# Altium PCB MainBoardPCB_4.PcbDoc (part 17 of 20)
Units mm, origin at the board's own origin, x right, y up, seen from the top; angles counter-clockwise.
Board outline 333.63 x 349.38 mm, 16 copper layers (L1, L2 (GND), L3 (Sign), L4 (GND), L5 (Sign), L6 (PWR/GND), L7(PWR/GND), L8 (Plane_GND), L9 (PWR/GND), L10 (PWR/GND), L11 (PWR/GND), L12 (Sign), L13 (GND), L14 (Sign), L15 (GND), L16), stack 2.502 mm thick; 2205 components, 1648 nets, 8314 pads, 3172 vias.
Unrouted connection lines stored in the file: 5141.
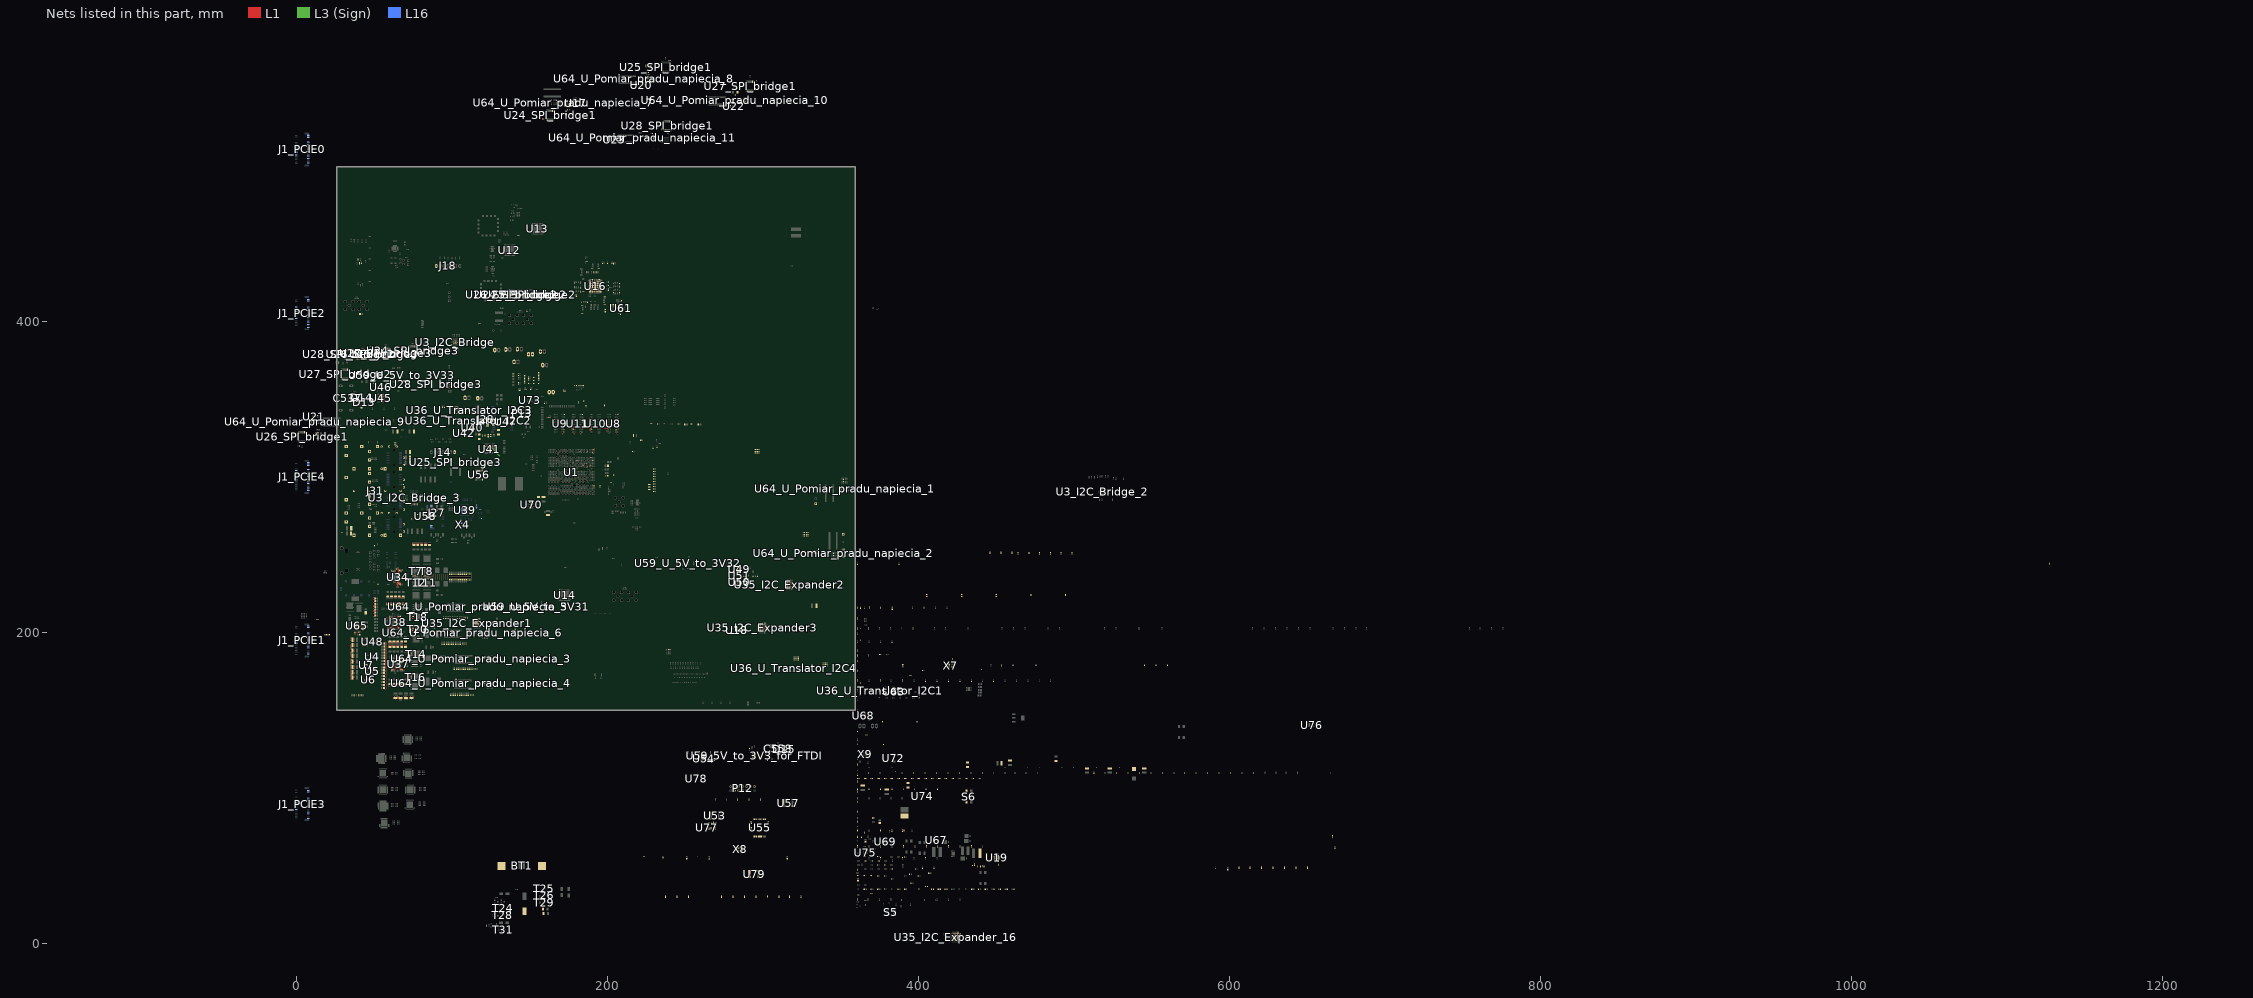
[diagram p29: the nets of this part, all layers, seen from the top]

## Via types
v1: diameter 0.5, hole 0.2, L1 to L16, tented both sides, 1153 vias
v2: diameter 0.5/0.35/0.35/0.35/0.35/0.35/0.35/0.35/0.35/0.35/0.35/0.35/0.35/0.35/0.35/0.5 (per signal layer), hole 0.2, L1 to L16, tented both sides, 548 vias
v3: diameter 0.5, hole 0.2, L1 to L16, 522 vias
v4: diameter 0.5/0.35/0.35/0.35/0.35/0.35/0.35/0.35/0.35/0.35/0.35/0.35/0.35/0.35/0.35/0.5 (per signal layer), hole 0.15, L1 to L16, tented both sides, 266 vias
v5: diameter 0.8, hole 0.4, L1 to L16, tented both sides, 164 vias
v6: diameter 0.35/0/0.35 (per signal layer), hole 0.127, L1 to L3 (Sign), tented both sides, 132 vias
v7: diameter 2.54, hole 1.02, L1 to L16, 125 vias
v8: diameter 1.4, hole 0.5, L1 to L16, tented both sides, 80 vias
v9: diameter 0.35, hole 0.127, L1 to L2 (GND), tented both sides, 36 vias
v10: diameter 0.4, hole 0.2, L1 to L16, 16 vias
v11: diameter 0.25, hole 0.2, L1 to L16, 16 vias
v12: diameter 5, hole 3, L1 to L16, 15 vias
v13: diameter 0.3, hole 0.2, L1 to L16, 15 vias
v14: diameter 0.45, hole 0.15, L1 to L16, 12 vias
v15: diameter 0.5/0.35/0.35/0.35/0.35/0.35/0.35/0.35/0.35/0.35/0.35/0.35/0.35/0.35/0.35/0.45 (per signal layer), hole 0.15, L1 to L16, tented both sides, 10 vias
v16: diameter 0.2/0/0.2 (per signal layer), hole 0.1, L1 to L3 (Sign), tented both sides, 9 vias
v17: diameter 0.4, hole 0.1, L1 to L16, 7 vias
v18: diameter 0.5, hole 0.2, L3 (Sign) to L6 (PWR/GND), tented both sides, 6 vias
v19: diameter 1.65, hole 1.65, L1 to L16, 6 vias
v20: diameter 1.15, hole 1.15, L1 to L16, 6 vias
v21: diameter 0.35/0/0.35 (per signal layer), hole 0.127, L14 (Sign) to L16, tented both sides, 5 vias
v22: diameter 0.2, hole 0.1, L1 to L16, 4 vias
v23: diameter 0.4, hole 0.2, L1 to L16, tented both sides, 2 vias
v24: diameter 0.4, hole 0.15, L1 to L16, 2 vias
v25: diameter 0.508, hole 0.127, L1 to L2 (GND), 2 vias
v26: diameter 0.508, hole 0.127, L2 (GND) to L3 (Sign), 2 vias
v27: diameter 0.5/0.35/0.35/0.35/0.35/0.35/0.35/0.35/0.35/0.35/0.35/0.35/0.35/0.35/0.35/0.5 (per signal layer), hole 0.15, L1 to L16, 2 vias
v28: diameter 0.35, hole 0.127, L3 (Sign) to L6 (PWR/GND), tented both sides, 2 vias
v29: diameter 5.5, hole 3.5, L1 to L16, 1 vias
v30: diameter 0.5/0.35/0.35/0.35/0.35/0.35/0.35/0.35/0.35/0.35/0.35/0.35/0.35/0.35/0.35/0.5 (per signal layer), hole 0.2, L1 to L16, 1 vias
v31: diameter 0.35/0.35/0.35 (per signal layer), hole 0.127, L1 to L3 (Sign), tented both sides, 1 vias
v32: diameter 0.45/0/0.45 (per signal layer), hole 0.15, L1 to L3 (Sign), tented both sides, 1 vias
v33: diameter 0.45/0/0.45 (per signal layer), hole 0.2, L14 (Sign) to L16, tented both sides, 1 vias
v34: diameter 0.35, hole 0.127, L2 (GND) to L3 (Sign), 1 vias
v35: diameter 0.35, hole 0.127, L1 to L2 (GND), 1 vias

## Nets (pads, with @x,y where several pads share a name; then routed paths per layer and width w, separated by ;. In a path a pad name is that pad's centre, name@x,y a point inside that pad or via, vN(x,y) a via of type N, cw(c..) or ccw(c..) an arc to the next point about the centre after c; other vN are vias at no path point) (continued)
eMMC_GND: B1.2 BT1.1 C4.2 C5.2 C6.2 C7.2 C8.1 C9.1 C10.1 C11.1 C12.2 C13.2 C14.2 C15.2 C16.1 C17.1 C18.1 C19.1 C20.1 C21.1 C22.1 C23.1 C24.1 C25.1 C26.1 C27.1 C28.1 C29.1 C30.1 C31.1 C32.1 C33.1 C34.1 C35.1 C37.1 C38.2 C39.1 C40.2 C207.1 C208.2 C209.1 C210.2 C211.1 C212.2 C213.1 C214.2 C215.1 C216.2 C217.1 C218.2 C219.2 C220.2 C221.2 C222.2 C223.1 C224.1 C225.1 C226.1 C227.1 C228.1 C229.1 C230.1 C231.1 C232.1 C233.1 C234.1 C235.1 C236.1 C237.1 C238.1 C239.1 C240.1 C241.1 C242.1 C243.2 C244.2 C245.2 C246.2 C247.1 C248.1 C249.1 C250.1 C251.1 C252.1 C253.1 C254.1 C255.1 C256.1 C257.1 C258.1 C259.1 C260.1 C261.1 C262.1 C263.1 C264.1 C265.1 C266.1 C303_I2C_Bridge.1 C303_I2C_Bridge_2.1 C303_I2C_Bridge_3.1 C304.2 C305.2 C306.2 C307.2 C308.1 C309_U_Pomiar_pradu_napiecia_1.1 C309_U_Pomiar_pradu_napiecia_2.1 C309_U_Pomiar_pradu_napiecia_3.1 C309_U_Pomiar_pradu_napiecia_4.1 C309_U_Pomiar_pradu_napiecia_5.1 C309_U_Pomiar_pradu_napiecia_6.1 C309_U_Pomiar_pradu_napiecia_7.1 C309_U_Pomiar_pradu_napiecia_8.1 C309_U_Pomiar_pradu_napiecia_9.1 C309_U_Pomiar_pradu_napiecia_10.1 C309_U_Pomiar_pradu_napiecia_11.1 C310.1 C311_I2C_Expander1.1 C311_I2C_Expander2.1 C311_I2C_Expander3.1 C311_I2C_Expander?.1 C311_I2C_Expander_10.1 C311_I2C_Expander_11.1 C311_I2C_Expander_12.1 C311_I2C_Expander_13.1 C311_I2C_Expander_14.1 C311_I2C_Expander_15.1 C311_I2C_Expander_16.1 C331.1 C332.1 C347.1 C348.1 C352.1 C353.1 C354.1 C355.1 C358.1 C359.1 C360.1 C361.1 C362.1 C363.1 C364.1 C365.1 C366.1 C367.1 C368.1 C369.1 C370.1 C371.1 C372.1 C373.1 C374.1 C375.1 C376.1 C377.1 C378.1 C379.1 C380.1 C381.1 C382.1 C383.1 C384.1 C385.1 C386.1 C387.1 C388.1 C391.2 C392.1 C396.1 C397.2 C399.2 C400.1 C401.1 C402.1 C403.1 C404.1 C405.1 C406.1 C407.1 C408.1 C409.1 C410.1 C411.1 C412.1 C413.1 C414.1 C415.1 C416.1 C417.1 C418.1 C419.1 C420.1 C421.1 C422.1 C423.1 C424.1 C425.1 C426.1 C427.1 C428.1 C429.1 C432.2 C433.1 C437.1 C438.2 C440.2 C441.1 C442.1 C443.1 C444.1 C445.1 C446.1 C447.1 C448.1 C449.1 C450.1 C451.1 C452.1 C453.1 C454.1 C455.1 C456.1 C457.1 C458.1 C459.1 C460.1 C461.1 C462.1 C463.1 C464.1 C465.1 C466.1 C467.1 C468.1 C469.1 C470.1 C471.1 C472.1 C473.1 C474.1 C480.1 C481.1 C485.1 C486.1 C487.1 C488.1 C489.1 C490.1 C491.1 C492.1 C493.1 C494.1 C495.1 C496.1 C497.1 C498.1 C499.1 C500.1 C501.1 C502.1 C503.1 C504.1 C505.1 C506.1 C507.1 C508.1 C509.1 C510.1 C511.1 C512.1 C513.1 C514.1 C515.1 C516.1 C517.1 C518.1 C519.1 C520.1 C521.1 C522.1 C523.1 C524.1 C537.7 C538.1 C539.1 C544.1 C545.1 C546.1 C547.1 C550.1 C551.1 C552.1 C553.1 C554.1 C555.1 C561.1 C562.1 C585.1 C586.1 C587.1 C606.1 C607.1 C609.1 C610.1 C611.1 C613.1 C614.1 C615.1 C617.1 C618.1 C619.1 C620.1 C621.1 C622.1 C623.1 C624.1 C625.1 C626.1 C631.1 C632.1 C633.1 C636.1 C637.1 C638.1 C645.1 C646.1 C654.1 C655.2 C656.2 C657.2 C674.1 C675.1 C676.1 C678.1 C679.1 C680.1 C705.1 C707.1 C708.1 C709.1 C711.1 C712.1 C719.1 C720.1 C721.1 C722.1 C723.1 C728.1 C729.1 C730.1 C731.1 C732.1 C733.1 C734.1 C735.1 C736.1 C737.1 C738.2 C739.2 C740.1 C741.1 C742.2 C743.1 C744.1 C745.1 C746.1 C747.2 C748.1 C749.1 C750.1 C751.2 C752.1 C753.2 C754.1 C755.1 C756.1 C757.2 C758.1 C759.1 C760.2 C761.1 C762.2 C763.1 C764.2 C765.1 C766.2 C767.2 C768.2 C769.2 C770.1 C771.1 C772.1 C773.1 C774.1 C775.1 C776.1 C777.1 C778.1 C779.1 C780.1 C781.1 C782.1 C783.1 C784.1 C785.1 C786.1 C787.1 C788.1 C789.1 C792.1 D13.3 D14.3 D14.8 D15.3 FB27.1 FB28.2 FB29.1 FB35.1 FB36.1 FB39.1 FB41.1 J14.1 J15.1 J16.1 J17.1 J18.1 J19.1 J20.1 J21.1 J22.1 J23.1 J24.1 J27.1 J27.3 J27.9 J27.15 J27.21 J27.27 J27.33 J27.39 J27.45 J27.51 J27.57 J27.63 J27.65 J27.67 J28.6 J31.SH1 J31.SH2 J31.SH3 J31.SH4 J31.SH5 J31.SH6 J31.SH7 J31.SH8 J31.SH9 J31.SH10 J31.SH11 J31.SH12 J31.SH13 J31.SH14 J31.SH15 J31.SH16 J31.SH17 J31.SH18 J31.SH19 J31.SH20 J31.SH21 J31.SH22 J31.SH23 J31.SH24 J31.SH25 J31.SH26 J31.SH27 J31.SH28 J31.SH29 J31.SH30 J31.SH31 J31.SH32 J31.SH33 J31.SH34 J31.SH35 J31.SH36 J31.SH37 J31.SH38 J31.SH39 J31.SH40 J31.SH41 J31.SH42 J31.SH43 J31.SH44 J31.SH45 J31.SH46 P7.1 P9.1 P11.2 P12.2 P12.4 P12.6 P12.8 P12.10 P12.12 P12.14 R2.1 R14.1 R18.1 R19.1 R21.1 R23.1 R25.1 R26.1 R27.1 R28.1 R56.2 R60.2 R61.2 R62.2 R63.2 R64.2 R73.1 R74.1 R109.1 R114.1 R129.2 R139.1 R167.2 R168.2 R170.2 R172.2 R173.2 R174.1 R178.1 R182.1 R183.1 R187.1 R191.1 R192.1 R196.1 R200.1 R201.1 R205.1 R209.1 R210.1 R214.1 R217.1 R218.1 R228.1 R229.1 R242.2 R244.2 R267.1 R269.1 R274.1 R275.1 R279.2 R280.1 R282.2 R284.1 R292.1 R299.1 R304.1 R317.1 R325.1 R326.1 R327.1 R328.1 R334.2 R341.1 R344.1 R345.1 R379.1 R380.1 R393.1 R396.1 R399.1 R400.2 R450.2 R452.2 R454.2 R456.2 R460.2 R461.1 R464.2 R467.1 R470.2 R472.2 R474.2 R476.2 R478.2 R480.2 R493.2 R495.2 R497.2 R501.2 R503.2 R505.2 R509.2 R511.2 R513.2 R517.2 R519.2 R521.2 R525.2 R527.2 R529.2 R561.1 R565.1 R569.1 R573.1 R577.1 R581.1 R585.1 R589.1 R595.1 R601.1 R629.1 R645.1 R652.1 R668.1 R672.1 R674.1 R675.1 R681.1 R682.1 R683.1 R684.1 R685.1 R690.1 R693.2 R696.2 R698.2 R700.2 R702.2 R704.2 R706.2 R708.2 R714.1 R739.2 R741.2 R743.2 R759.2 R761.2 R763.2 R764.1 R838.2 R840.2 R841.2 S6.1 S6.2 T7.1 T7.2 T7.3 T8.1 T8.2 T8.3 T11.1 T11.2 T11.3 T12.1 T12.2 T12.3 T14.1 T14.2 T14.3 T16.1 T16.2 T16.3 T18.1 T18.2 T18.3 T20.1 T20.2 T20.3 T24.2 T25.2 T26.2 T28.2 T29.2 T31.2 U1.A1 U1.A2 U1.A5 U1.A9 U1.A11 U1.A30 U1.AA9 U1.AA19 U1.AA29 U1.AB2 U1.AB7 U1.AB12 U1.AB17 U1.AB22 U1.AC5 U1.AC10 U1.AC20 U1.AD13 U1.AD18 U1.AD23 U1.AE6 U1.AE16 U1.AE21 U1.AF4 U1.AF9 U1.AF19 U1.AF24 U1.AF29 U1.AG2 U1.AG12 U1.AG22 U1.AH5 U1.AH15 U1.AH20 U1.AH25 U1.AJ3 U1.AJ8 U1.AJ13 U1.AJ18 U1.AJ23 U1.AJ28 U1.AK1 U1.AK30 U1.B3 U1.B4 U1.B7 U1.B11 U1.B13 U1.B17 U1.C1 U1.C2 U1.C5 U1.C9 U1.C11 U1.C15 U1.C20 U1.C25 U1.C30 U1.D3 U1.D4 U1.D7 U1.D11 U1.E1 U1.E2 U1.E5 U1.E9 U1.E11 U1.F3 U1.F4 U1.F7 U1.F11 U1.F14 U1.F24 U1.F25 U1.F26 U1.F27 U1.F28 U1.F29 U1.F30 U1.G1 U1.G2 U1.G5 U1.G9 U1.G11 U1.G17 U1.G22 U1.G23 U1.G24 U1.G27 U1.G28 U1.H3 U1.H4 U1.H7 U1.H11 U1.H20 U1.H22 U1.H26 U1.H29 U1.H30 U1.J1 U1.J2 U1.J5 U1.J9 U1.J10 U1.J11 U1.J13 U1.J22 U1.J24 U1.J27 U1.J28 U1.K3 U1.K4 U1.K9 U1.K22 U1.K26 U1.K29 U1.K30 U1.L1 U1.L2 U1.L5 U1.L9 U1.L12 U1.L16 U1.L18 U1.L22 U1.L24 U1.L28 U1.M3 U1.M4 U1.M7 U1.M9 U1.M11 U1.M13 U1.M15 U1.M17 U1.M22 U1.M26 U1.M29 U1.M30 U1.N1 U1.N2 U1.N5 U1.N9 U1.N12 U1.N14 U1.N16 U1.N23 U1.N24 U1.N25 U1.N26 U1.N27 U1.N28 U1.N29 U1.N30 U1.P3 U1.P4 U1.P7 U1.P9 U1.P11 U1.P13 U1.P15 U1.P17 U1.R1 U1.R2 U1.R5 U1.R9 U1.R12 U1.R16 U1.R21 U1.R26 U1.T3 U1.T4 U1.T7 U1.T8 U1.T11 U1.T13 U1.T17 U1.T19 U1.T24 U1.T29 U1.U1 U1.U2 U1.U5 U1.U7 U1.U12 U1.U16 U1.U22 U1.U27 U1.V3 U1.V4 U1.V7 U1.V9 U1.V11 U1.V13 U1.V20 U1.V25 U1.W1 U1.W2 U1.W5 U1.W6 U1.W12 U1.W14 U1.W16 U1.W18 U1.W23 U1.W28 U1.Y2 U1.Y3 U1.Y4 U1.Y5 U1.Y11 U1.Y13 U1.Y15 U1.Y21 U1.Y26 U3_I2C_Bridge.9 U3_I2C_Bridge.25 U3_I2C_Bridge_2.9 U3_I2C_Bridge_2.25 U3_I2C_Bridge_3.9 U3_I2C_Bridge_3.25 U4.3 U4.6 U4.12 U5.3 U5.6 U5.12 U6.A1 U6.A4 U6.B1 U6.B2 U6.B3 U6.B4 U6.C4 U7.A1 U7.A4 U7.B1 U7.B2 U7.B3 U7.B4 U7.C4 U8.A2 U8.A5 U8.B2 U8.C6 U8.D2 U8.D5 U8.E1 U8.E3 U8.E5 U8.E6 U8.F1 U8.G5 U8.H1 U8.H6 U8.K1 U8.K6 U8.M6 U8.N1 U8.T1 U9.A2 U9.A5 U9.B2 U9.C6 U9.D2 U9.D5 U9.E1 U9.E3 U9.E5 U9.E6 U9.F1 U9.G5 U9.H1 U9.H6 U9.K1 U9.K6 U9.M6 U9.N1 U9.T1 U10.A2 U10.A5 U10.B2 U10.C6 U10.D2 U10.D5 U10.E1 U10.E3 U10.E5 U10.E6 U10.F1 U10.G5 U10.H1 U10.H6 U10.K1 U10.K6 U10.M6 U10.N1 U10.T1 U11.A2 U11.A5 U11.B2 U11.C6 U11.D2 U11.D5 U11.E1 U11.E3 U11.E5 U11.E6 U11.F1 U11.G5 U11.H1 U11.H6 U11.K1 U11.K6 U11.M6 U11.N1 U11.T1 U15.2 U15.10 U17.A1 U17.A4 U17.B1 U17.B2 U17.B3 U17.B4 U17.C4 U18.A1 U18.A4 U18.B1 U18.B2 U18.B3 U18.B4 U18.C4 U19.10 U19.18 U19.27 U19.29 U20.A1 U20.A4 U20.B1 U20.B2 U20.B3 U20.B4 U20.C4 U21.A1 U21.A4 U21.B1 U21.B2 U21.B3 U21.B4 U21.C4 U22.A1 U22.A4 U22.B1 U22.B2 U22.B3 U22.B4 U22.C4 U23.A1 U23.A4 U23.B1 U23.B2 U23.B3 U23.B4 U23.C4 U24_SPI_bridge1.2 U24_SPI_bridge1.10 U24_SPI_bridge2.2 U24_SPI_bridge2.10 U24_SPI_bridge3.2 U24_SPI_bridge3.10 U25_SPI_bridge1.2 U25_SPI_bridge1.10 U25_SPI_bridge2.2 U25_SPI_bridge2.10 U25_SPI_bridge3.2 U25_SPI_bridge3.10 U26_SPI_bridge1.2 U26_SPI_bridge1.10 U26_SPI_bridge2.2 U26_SPI_bridge2.10 U26_SPI_bridge3.2 U26_SPI_bridge3.10 U27_SPI_bridge1.2 U27_SPI_bridge1.10 U27_SPI_bridge2.2 U27_SPI_bridge2.10 U27_SPI_bridge3.2 U27_SPI_bridge3.10 U28_SPI_bridge1.2 U28_SPI_bridge1.10 U28_SPI_bridge2.2 U28_SPI_bridge2.10 U28_SPI_bridge3.2 U28_SPI_bridge3.10 U34.19 U34.22 U35_I2C_Expander1.6 U35_I2C_Expander1.29 U35_I2C_Expander2.6 U35_I2C_Expander2.29 U35_I2C_Expander3.6 U35_I2C_Expander3.29 U35_I2C_Expander_16.6 U35_I2C_Expander_16.29 U36_U_Translator_I2C1.1 U36_U_Translator_I2C2.1 U36_U_Translator_I2C3.1 U36_U_Translator_I2C4.1 U37.19 U37.22 U38.19 U38.22 U39.49 U40.4 U40.9 U41.A6 U41.C4 U41.E7 U41.G5 U41.H10 U41.J5 U41.K8 U41.N2 U41.N5 U41.P4 U41.P6 U42.4 U42.9 U45.23 U45.33 U46.A1 U46.A4 U46.B1 U46.B2 U46.B4 U47.C3 U48.12 U49.4 U49.9 U50.4 U50.9 U51.4 U51.9 U58.2 U58.3 U58.6 U58.7 U63.2 U63.8 U64_U_Pomiar_pradu_napiecia_1.7 U64_U_Pomiar_pradu_napiecia_2.7 U64_U_Pomiar_pradu_napiecia_3.7 U64_U_Pomiar_pradu_napiecia_4.7 U64_U_Pomiar_pradu_napiecia_5.7 U64_U_Pomiar_pradu_napiecia_6.7 U64_U_Pomiar_pradu_napiecia_7.7 U64_U_Pomiar_pradu_napiecia_8.7 U64_U_Pomiar_pradu_napiecia_9.7 U64_U_Pomiar_pradu_napiecia_10.7 U64_U_Pomiar_pradu_napiecia_11.7 U67.2 U68.2 U69.6 U69.17 U70.3 U70.8 U70.13 U70.18 U70.21 U72.7 U73.4 U73.9 U74.3 U75.3 U78.2 X4.2 X4.4 X7.2 X7.4 | length 264.9
  L1 w0.116: v2(177.909,309.05) U1.U22@178.397,309.537 ; v2(179.909,310.052) U1.W23@180.397,310.539 ; v2(183.909,307.052) U1.AC20@184.397,307.539 ; v2(185.909,308.052) U1.AE21@186.397,308.539 ; v2(186.909,306.052) U1.AF19@187.397,306.539 ; v2(186.909,316.052) U1.AF29@187.397,316.539 ; v2(188.909,307.052) U1.AH20@189.397,307.539 ; U1.AH25@189.397,312.539 v2(189.884,313.027) ; v2(189.909,305.052) U1.AJ18@190.397,305.539 ; U1.AJ23@190.397,310.539 v2(190.884,311.027) ; U1.AJ28@190.397,315.539 v2(190.884,315.052) ; U1.AK30@191.397,317.539 v2@191.884,318.027 ; v4@206.343,327.774 v4(206.35,327.774) ; U8.E1@206.857,331.26 U8.E1@206.863,331.254
  L1 w0.2: U9.H6@166.076,333.66 v9(166.076,333.667) ; U9.E3@170.876,331.26 v9(170.876,331.268) ; U11.H6@177.536,333.66 v9(177.536,333.664) ; v9(183.134,330.46) U11.D2@183.136,330.46 ; v9(183.394,309.542) U1.AB22@183.397,309.539 ; v9(183.934,333.663) U11.H1@183.936,333.66 ; U10.A5@189.797,328.06 v9(189.797,328.063) ; v9(200.449,333.66) U8.H6@200.457,333.66 ; v9(205.251,331.26) U8.E3@205.257,331.26 ; v4(205.684,330.088) U8.D2@206.057,330.46 ; U8.F1@206.857,332.06 v4(207.428,332.06) ; U8.H1@206.857,333.66 v4(207.261,334.064) ; U8.K1@206.857,335.26 v4(207.261,335.664) ; U8.N1@206.857,337.66 v4(207.261,338.064) ; U8.T1@206.857,340.06 v4(207.261,340.464) ; U8.E1@206.863,331.254 v4(207.645,331.254)
  L1 w0.25: v1(161.216,338.184) R56.2@162.46,338.184 ; v4(171.272,327.657) U9.A2@171.676,328.06 ; v4(171.272,328.457) U9.B2@171.676,328.86 ; U9.D2@171.676,330.46 v4(172.079,330.864) ; v4(177.133,329.257) U11.C6@177.536,329.66 ; v4(177.133,330.857) U11.E6@177.536,331.26 ; v4(177.933,330.857) U11.E5@178.336,331.26 ; U11.A5@178.336,328.06 178.74,327.657 ; v1(181.909,317.027) U1.AA29@182.397,316.539 ; v4(182.733,327.657) U11.A2@183.136,328.06 ; v4(182.733,328.457) U11.B2@183.136,328.86 ; U11.E1@183.936,331.26 v4(184.507,331.26) ; U11.F1@183.936,332.06 v4(184.507,332.06) ; U11.N1@183.936,337.66 v4(184.34,338.064) ; v4(188.593,330.064) U10.C6@188.997,329.66 ; v4(188.593,331.664) U10.E6@188.997,331.26 ; v4(188.593,334.064) U10.H6@188.997,333.66 ; v4(188.593,337.264) U10.M6@188.997,336.86 ; v4(189.393,330.864) U10.D5@189.797,330.46 ; v4(189.393,331.664) U10.E5@189.797,331.26 ; U10.G5@189.797,332.86 v4(190.2,332.457) ; U8.A2@206.057,328.06 v4@206.343,327.774
  L1 w0.254: U64_U_Pomiar_pradu_napiecia_3.7@116.278,183.659 v5(117.754,183.659) ; U1.AF24@187.397,311.539 v9(187.401,311.535) ; v9(188.394,309.539) U1.AG22@188.397,309.539 ; v1@198.406,331.26 v1(198.495,331.26) U8.E6@200.457,331.26 ; v1(198.653,333.858) v1@198.761,333.858
  L1 w0.3: U1.AD23@185.397,310.539 v9(185.397,310.548) ; U10.E3@193.797,331.26 v1(194.195,331.659) ; U10.D2@194.597,330.46 v9(194.599,330.463) ; U10.E1@195.397,331.26 v9(195.397,331.268) ; U8.B2@206.057,328.86 v9(206.057,328.878)
  L1 w0.5: v1(35.023,183.811) C12.2@36.11,183.811 ; v1(35.023,184.916) C12.2@36.11,184.916 ; v1(35.023,186.012) C12.2@36.11,186.012 ; v1(35.023,187.256) C15.2@36.11,187.256 ; v1(35.023,188.361) C15.2@36.11,188.361 ; v1(35.023,189.458) C15.2@36.11,189.457 ; v1(35.023,190.701) C13.2@36.11,190.701 ; v1(35.023,191.806) C13.2@36.11,191.806 ; v1(35.023,192.903) C13.2@36.11,192.903 ; v1(35.023,194.146) C14.2@36.11,194.146 ; v1(35.023,195.251) C14.2@36.11,195.251 ; v1(35.023,196.348) C14.2@36.11,196.348 ; v1(35.104,169.788) C4.2@36.191,169.788 ; v1(35.104,170.893) C4.2@36.191,170.893 ; v1(35.104,171.99) C4.2@36.191,171.99 ; v1(35.104,173.243) C5.2@36.191,173.243 ; v1(35.104,174.348) C5.2@36.191,174.348 ; v1(35.104,175.445) C5.2@36.191,175.445 ; v1(35.104,176.697) C7.2@36.191,176.697 ; v1(35.104,177.802) C7.2@36.191,177.802 ; v1(35.104,178.899) C7.2@36.191,178.899 ; v1(35.104,180.152) C6.2@36.191,180.152 ; v1(35.104,181.257) C6.2@36.191,181.257 ; v1(35.104,182.353) C6.2@36.191,182.353 ; C12.2@36.11,184.359 v1(37.197,184.359) ; C12.2@36.11,185.464 v1(37.197,185.464) ; C15.2@36.11,187.804 v1(37.197,187.804) ; C15.2@36.11,188.909 v1(37.197,188.909) ; C13.2@36.11,191.249 v1(37.197,191.249) ; C13.2@36.11,192.354 v1(37.197,192.354) ; C14.2@36.11,194.694 v1(37.197,194.694) ; C14.2@36.11,195.799 v1(37.197,195.799) ; C4.2@36.191,170.337 v1(37.278,170.337) ; C4.2@36.191,171.442 v1(37.278,171.442) ; C5.2@36.191,173.791 v1(37.278,173.791) ; C5.2@36.191,174.896 v1(37.278,174.896) ; C7.2@36.191,177.246 v1(37.278,177.246) ; C7.2@36.191,178.351 v1(37.278,178.351) ; C6.2@36.191,180.7 v1(37.278,180.7) ; C6.2@36.191,181.805 v1(37.278,181.805) ; v5(42.6,191.22) R683.1@42.6,192.033 ; R685.1@42.6,195.933 v5(42.6,196.747) ; R684.1@44.716,195.933 v5(44.716,196.747) ; v5(45.775,191.22) R682.1@45.775,192.033 ; v5(46.946,174.081) 47.391,174.081 U5.6@47.56,174.25 ; v5(46.946,175.918) 47.391,175.918 U5.3@47.56,175.75 ; v5(46.946,183.403) 47.391,183.403 U4.6@47.56,183.571 ; v5(46.946,185.24) 47.391,185.24 U4.3@47.56,185.071 ; v1(49.579,210.588) C780.1@50.666,210.588 ; v1(49.579,211.312) C780.1@50.665,211.312 ; v1(49.579,212.483) C779.1@50.666,212.483 ; v1(49.579,213.207) C779.1@50.666,213.207 ; v1(49.579,214.293) C778.1@50.666,214.293 ; v1(49.579,215.016) C778.1@50.666,215.016 ; v1(49.579,216.83) C777.1@50.666,216.83 ; v1(49.579,217.851) C776.1@50.666,217.851 ; v1(49.579,218.575) C776.1@50.666,218.575 ; v1(49.579,219.674) C775.1@50.666,219.674 ; v1(49.579,220.398) C775.1@50.666,220.398 ; v1(49.579,221.488) C774.1@50.666,221.488 ; v1(49.579,222.211) C774.1@50.666,222.211 ; v1(49.579,216.106) C777.1@50.666,216.106 ; U48.12@49.827,194.733 49.996,194.902 v5(50.442,194.902) ; U5.12@49.86,175.75 50.029,175.918 v5(50.475,175.918) ; U4.12@49.86,185.071 50.029,185.24 v5(50.475,185.24) ; R681.1@52.018,194.019 v5(52.018,194.833) ; C20.1@56.419,164.502 v1(57.506,164.502) ; C20.1@56.419,163.778 v1(57.506,163.778) ; C27.1@56.447,165.786 v1(57.534,165.786) ; C27.1@56.446,166.51 v1(57.533,166.51) ; C22.1@56.447,167.684 v1(57.534,167.684) ; C22.1@56.446,168.408 v1(57.533,168.408) ; C21.1@56.447,169.581 v1(57.534,169.581) ; C21.1@56.446,170.305 v1(57.533,170.305) ; C24.1@56.447,171.479 v1(57.534,171.479) ; C24.1@56.446,172.203 v1(57.533,172.203) ; C25.1@56.447,173.377 v1(57.534,173.377) ; C25.1@56.446,174.101 v1(57.533,174.101) ; C23.1@56.447,175.275 v1(57.534,175.275) ; C23.1@56.446,175.999 v1(57.533,175.999) ; C31.1@56.458,179.934 v1(57.545,179.934) ; C30.1@56.458,181.831 v1(57.545,181.831) ; C32.1@56.458,183.729 v1(57.545,183.729) ; C29.1@56.458,185.627 v1(57.545,185.627) ; C28.1@56.458,187.525 v1(57.545,187.525) ; C33.1@56.458,189.423 v1(57.545,189.423) ; C34.1@56.458,191.321 v1(57.545,191.321) ; C31.1@56.459,179.21 v1(57.546,179.21) ; C30.1@56.459,181.108 v1(57.546,181.108) ; C32.1@56.459,183.005 v1(57.546,183.005) ; C29.1@56.459,184.903 v1(57.546,184.903) ; C28.1@56.459,186.801 v1(57.546,186.801) ; C33.1@56.459,188.699 v1(57.546,188.699) ; C34.1@56.459,190.597 v1(57.546,190.597) ; C26.1@56.477,177.173 v1(57.564,177.173) ; C26.1@56.476,177.897 v1(57.563,177.897) ; C35.1@56.484,193.263 v1(57.571,193.263) ; C35.1@56.484,192.539 v1(57.571,192.539) ; v1(58.138,222.101) C392.1@58.138,223.188 ; C397.2@58.206,217.883 v1(58.206,218.97) ; v1(58.776,222.101) C392.1@58.776,223.188 ; C397.2@58.852,217.883 v1(58.852,218.97) ; v1(59.421,222.101) C392.1@59.421,223.188 ; C397.2@59.489,217.883 v1(59.489,218.97) ; v1(59.638,165.636) C433.1@59.638,166.723 ; C438.2@59.645,190.731 v1(59.645,191.818) ; v1(59.653,193.043) C353.1@59.653,194.13 ; v1(60.276,165.636) C433.1@60.276,166.723 ; C438.2@60.29,190.731 v1(60.29,191.818) ; v1(60.29,193.043) C353.1@60.29,194.13 ; v1(60.62,222.101) C391.2@60.62,223.188 ; C396.1@60.688,217.883 v1(60.688,218.97) ; v1(60.921,165.636) C433.1@60.921,166.723 ; C438.2@60.927,190.731 v1(60.927,191.818) ; v1(60.936,193.043) C353.1@60.936,194.13 ; v1(61.258,222.101) C391.2@61.258,223.188 ; C396.1@61.334,217.883 v1(61.334,218.97) ; v1(61.903,222.101) C391.2@61.903,223.188 ; C396.1@61.971,217.883 v1(61.971,218.97) ; v1(62.12,165.636) C432.2@62.12,166.723 ; C437.1@62.127,190.731 v1(62.127,191.818) ; v1(62.135,193.043) C352.1@62.135,194.13 ; C769.2@62.575,157.849 v1(62.575,158.936) ; v1(62.758,165.636) C432.2@62.758,166.723 ; C437.1@62.772,190.731 v1(62.772,191.818) ; v1(62.772,193.043) C352.1@62.772,194.13 ; v1(63.102,222.1) C405.1@63.102,223.187 ; v1(63.124,156.762) C769.2@63.124,157.849 ; C402.1@63.17,217.883 v1(63.17,218.97) ; v1(63.403,165.636) C432.2@63.403,166.723 ; C437.1@63.409,190.731 v1(63.409,191.818) ; v1(63.418,193.043) C352.1@63.418,194.13 ; C769.2@63.68,157.849 v1(63.68,158.936) ; v1(63.74,222.1) C405.1@63.74,223.187 ; C402.1@63.816,217.883 v1(63.816,218.97) ; v1(64.229,156.762) C769.2@64.229,157.849 ; v1(64.385,222.1) C405.1@64.385,223.187 ; C402.1@64.453,217.883 v1(64.453,218.97) ; v1(64.602,165.636) C446.1@64.602,166.723 ; C443.1@64.609,190.731 v1(64.609,191.818) ; v1(64.617,193.043) C374.1@64.617,194.13 ; C769.2@64.777,157.849 v1(64.777,158.936) ; v1(65.24,165.636) C446.1@65.24,166.723 ; C443.1@65.254,190.731 v1(65.254,191.818) ; v1(65.254,193.043) C374.1@65.254,194.13 ; v1(65.584,222.1) C404.1@65.584,223.187 ; C401.1@65.652,217.883 v1(65.652,218.97) ; v1(65.885,165.636) C446.1@65.885,166.723 ; C443.1@65.891,190.731 v1(65.891,191.818) ; v1(65.9,193.043) C374.1@65.9,194.13 ; C768.2@65.979,157.65 v1(65.979,158.737) ; v1(66.222,222.1) C404.1@66.222,223.187 ; C401.1@66.298,217.883 v1(66.298,218.97) ; v1(66.528,156.563) C768.2@66.528,157.65 ; v1(66.867,222.1) C404.1@66.867,223.187 ; C401.1@66.935,217.883 v1(66.935,218.97) ; C768.2@67.084,157.65 v1(67.084,158.737) ; v1(67.085,165.636) C445.1@67.085,166.723 ; C442.1@67.091,190.731 v1(67.091,191.818) ; v1(67.099,193.043) C371.1@67.099,194.13 ; v1(67.632,156.563) C768.2@67.632,157.65 ; v1(67.722,165.636) C445.1@67.722,166.723 ; C442.1@67.736,190.731 v1(67.736,191.818) ; v1(67.736,193.043) C371.1@67.736,194.13 ; v1(68.066,222.07) C403.1@68.066,223.157 ; C400.1@68.134,217.853 v1(68.134,218.94) ; C768.2@68.181,157.65 v1(68.181,158.737) ; v1(68.367,165.636) C445.1@68.367,166.723 ; C442.1@68.373,190.731 v1(68.373,191.818) ; v1(68.382,193.043) C371.1@68.382,194.13 ; v1(68.704,222.07) C403.1@68.704,223.157 ; C400.1@68.78,217.853 v1(68.78,218.94) ; v1(69.349,222.07) C403.1@69.349,223.157 ; C400.1@69.417,217.853 v1(69.417,218.94) ; C767.2@69.419,157.85 v1(69.419,158.937) ; v1(69.567,165.605) C444.1@69.567,166.692 ; C441.1@69.573,190.7 v1(69.573,191.787) ; v1(69.581,193.012) C376.1@69.581,194.099 ; v1(69.967,156.763) C767.2@69.967,157.85 ; v1(70.204,165.605) C444.1@70.204,166.692 ; C441.1@70.218,190.7 v1(70.218,191.787) ; v1(70.218,193.012) C376.1@70.218,194.099 ; C767.2@70.524,157.85 v1(70.524,158.937) ; v1(70.849,165.605) C444.1@70.849,166.692 ; C441.1@70.855,190.7 v1(70.855,191.787) ; v1(70.864,193.012) C376.1@70.864,194.099 ; v1(71.072,156.763) C767.2@71.072,157.85 ; C767.2@71.621,157.85 v1(71.621,158.937) ; C766.2@72.887,157.849 v1(72.887,158.936) ; v1(72.923,170.65) T16.3@74.01,170.65 ; v1(72.923,171.92) T16.2@74.01,171.92 ; v1(72.923,173.19) T16.1@74.01,173.19 ; v1(73.127,185.42) T14.3@74.214,185.42 ; v1(73.127,186.69) T14.2@74.214,186.69 ; v1(73.127,187.96) T14.1@74.214,187.96 ; v1(73.435,156.762) C766.2@73.435,157.849 ; v1(73.987,201.422) T20.3@75.074,201.422 ; v1(73.987,202.692) T20.2@75.074,202.692 ; v1(73.987,203.962) T20.1@75.074,203.962 ; C766.2@73.992,157.849 v1(73.992,158.936) ; v1(74.086,209.067) T18.3@75.173,209.067 ; v1(74.086,210.337) T18.2@75.173,210.337 ; v1(74.086,211.607) T18.1@75.173,211.607 ; v1(74.54,156.762) C766.2@74.54,157.849 ; C348.1@74.983,256.276 v1(74.983,257.362) ; C766.2@75.088,157.849 v1(75.088,158.936) ; C348.1@75.629,256.276 v1(75.629,257.362) ; C348.1@76.266,256.276 v1(76.266,257.362) ; C347.1@77.465,256.276 v1(77.465,257.363) ; C347.1@78.111,256.275 v1(78.111,257.363) ; C347.1@78.748,256.276 v1(78.748,257.363) ; C372.1@79.947,256.275 v1(79.947,257.362) ; C372.1@80.593,256.275 v1(80.593,257.362) ; C372.1@81.23,256.275 v1(81.23,257.362) ; C375.1@82.429,256.275 v1(82.429,257.362) ; C375.1@83.075,256.275 v1(83.075,257.362) ; C375.1@83.712,256.275 v1(83.712,257.362) ; C373.1@84.911,256.245 v1(84.911,257.332) ; C373.1@85.557,256.245 v1(85.557,257.332) ; C373.1@86.194,256.245 v1(86.194,257.332)
  L16 w0.254: v1(198.653,333.858) v1@198.704,333.858
  other v1: 75.092,233.907 76.352,233.907 77.612,233.907 78.872,233.907 82.032,233.914 83.292,233.914 84.552,233.914 85.812,233.914 87.072,234.379 88.332,234.379 89.591,234.379 90.851,234.379 92.111,234.379 93.371,234.379 94.631,234.379 95.891,234.379 97.151,234.379 98.4,234.848 99.089,234.848 99.779,234.848 100.469,234.848 101.159,234.848 101.848,234.848 102.538,234.848 103.228,234.848 103.918,234.848 104.607,234.848 105.297,234.848 105.987,234.848 106.677,234.848 107.366,234.848 108.056,234.848 108.746,234.848 109.436,234.848 110.125,234.848 110.815,234.848 111.505,234.848 112.195,234.848 75.092,235.632 76.352,235.632 77.612,235.632 78.872,235.632 80.488,235.639 82.032,235.639 83.292,235.639 84.552,235.639 85.812,235.639 87.072,235.639 88.332,235.639 89.591,235.639 90.851,235.639 92.111,235.639 93.371,235.639 94.631,235.639 95.891,235.639 97.151,235.639 98.411,235.639 99.101,235.639 99.79,235.639 100.48,235.639 101.17,235.639 101.86,235.639 102.55,235.639 103.239,235.639 103.929,235.639 104.619,235.639 105.309,235.639 105.998,235.639 106.688,235.639 107.378,235.639 108.068,235.639 108.757,235.639 109.447,235.639 110.137,235.639 110.827,235.639 111.516,235.639 112.206,235.639 98.411,236.461 99.101,236.461 99.79,236.461 100.48,236.461 101.17,236.461 101.86,236.461 102.55,236.461 103.239,236.461 103.929,236.461 104.619,236.461 105.309,236.461 105.998,236.461 106.688,236.461 107.378,236.461 108.068,236.461 108.757,236.461 109.447,236.461 110.137,236.461 110.827,236.461 111.516,236.461 112.206,236.461 87.072,236.899 88.332,236.899 89.591,236.899 90.851,236.899 92.111,236.899 93.371,236.899 94.631,236.899 95.891,236.899 97.151,236.899 75.129,237.339 76.389,237.339 77.649,237.339 78.909,237.339 82.069,237.346 83.328,237.346 84.588,237.346 85.848,237.346 179.397,312.539 181.397,313.539 202.619,326.479 199.72,329.552
  other v2: 162.397,288.539 164.397,288.539 166.397,288.539 168.397,288.539 170.397,288.539 172.397,288.539 174.397,288.539 176.397,288.539 178.397,288.539 180.397,288.539 191.397,288.539 162.397,289.539 164.397,289.539 166.397,289.539 168.397,289.539 170.397,289.539 172.397,289.539 174.397,289.539 176.397,289.539 178.397,289.539 180.397,289.539 181.397,289.539 183.397,289.539 188.397,289.539 163.397,290.539 165.397,290.539 167.397,290.539 169.397,290.539 171.397,290.539 173.397,290.539 175.397,290.539 177.397,290.539 179.397,290.539 181.397,290.539 190.397,290.539 163.397,291.539 165.397,291.539 167.397,291.539 169.397,291.539 171.397,291.539 173.397,291.539 175.397,291.539 177.397,291.539 179.397,291.539 181.397,291.539 187.397,291.539 162.397,292.539 164.397,292.539 166.397,292.539 168.397,292.539 170.397,292.539 172.397,292.539 174.397,292.539 176.397,292.539 178.397,292.539 180.397,292.539 181.397,292.539 184.397,292.539 189.397,292.539 180.397,293.539 186.397,293.539 163.397,294.539 165.397,294.539 167.397,294.539 169.397,294.539 173.397,294.539 175.397,294.539 177.397,294.539 178.397,294.539 179.397,294.539 183.397,294.539 177.397,295.539 190.397,295.539 162.397,296.539 164.397,296.539 166.397,296.539 168.397,296.539 170.397,296.539 171.397,296.539 172.397,296.539 173.397,296.539 174.397,296.539 175.397,296.539 176.397,296.539 179.397,296.539 182.397,296.539 187.397,296.539 170.397,297.539 184.397,297.539 162.397,298.539 163.397,298.539 164.397,298.539 165.397,298.539 166.397,298.539 167.397,298.539 168.397,298.539 169.397,298.539 170.397,298.539 173.397,298.539 175.397,298.539 177.397,298.539 179.397,298.539 181.397,298.539 172.397,299.539 174.397,299.539 176.397,299.539 178.397,299.539 180.397,299.539 183.397,299.539 188.397,299.539 163.397,300.539 170.397,300.539 173.397,300.539 175.397,300.539 177.397,300.539 179.397,300.539 181.397,300.539 185.397,300.539 190.397,300.539 167.397,301.539 174.397,301.539 180.397,301.539 164.397,302.539 173.397,302.539 175.397,302.539 181.397,302.539 189.397,302.539 172.397,303.539 174.397,303.539 176.397,303.539 178.397,303.539 180.397,303.539 186.397,303.539 163.397,304.539 168.397,304.539 173.397,304.539 175.397,304.539 177.397,304.539 183.397,304.539 172.397,305.539 180.397,305.539 185.397,305.539 177.397,306.539 182.397,306.539 164.397,307.539 169.397,307.539 179.397,307.539 176.397,308.539 181.397,308.539 168.397,309.539 169.397,309.539 170.397,309.539 171.397,309.539 172.397,309.539 173.397,309.539 168.397,310.539 174.397,310.539 167.397,311.539 168.397,311.539 170.397,311.539 172.397,311.539 174.397,311.539 177.397,311.539 164.397,312.539 167.397,312.539 174.397,312.539 167.397,313.539 169.397,313.539 171.397,313.539 173.397,313.539 174.397,313.539 176.397,313.539 167.397,314.539 168.397,314.539 170.397,314.539 174.397,314.539 178.397,314.539 167.397,315.539 168.397,315.539 170.397,315.539 172.397,315.539 174.397,315.539 180.397,315.539 167.397,316.539 169.397,316.539 171.397,316.539 173.397,316.539 174.397,316.539 177.397,316.539 162.397,317.539 164.397,317.539 167.397,317.539 169.397,317.539 171.397,317.539 173.397,317.539 174.397,317.539 191.789,317.932
  other v3: 422.421,2.45 423.521,2.45 424.622,2.45 425.722,2.45 422.421,3.55 423.521,3.55 424.622,3.55 425.722,3.55 422.421,4.65 423.521,4.65 424.622,4.65 425.722,4.65 422.421,5.75 423.521,5.75 424.622,5.75 425.722,5.75 449.881,54.043 450.981,54.043 449.881,55.143 450.981,55.143 449.881,56.243 450.981,56.243 378.182,64.701 379.282,64.701 378.182,65.801 379.282,65.801 297.925,201.163 299.025,201.163 300.125,201.163 301.225,201.163 297.925,202.263 299.025,202.263 300.125,202.263 301.225,202.263 297.925,203.363 299.025,203.363 300.125,203.363 301.225,203.363 114.517,204.214 115.617,204.214 116.717,204.214 117.817,204.214 297.925,204.463 299.025,204.463 300.125,204.463 301.225,204.463 114.517,205.314 115.617,205.314 116.717,205.314 117.817,205.314 114.517,206.414 115.617,206.414 116.717,206.414 117.817,206.414 114.517,207.514 115.617,207.514 116.717,207.514 117.817,207.514 315.304,229.007 316.404,229.007 317.504,229.007 318.604,229.007 315.304,230.107 316.404,230.107 317.504,230.107 318.604,230.107 315.304,231.207 316.404,231.207 317.504,231.207 318.604,231.207 284.331,231.604 285.331,231.604 315.304,232.307 316.404,232.307 317.504,232.307 318.604,232.307 284.331,232.604 285.331,232.604 284.458,235.864 285.458,235.864 284.458,236.864 285.458,236.864 284.458,240.182 285.458,240.182 284.458,241.182 285.458,241.182 107.614,276.725 108.984,276.725 106.499,277.84 107.614,277.84 108.984,277.84 110.099,277.84 106.499,279.21 107.614,279.21 108.984,279.21 110.099,279.21 107.614,280.325 108.984,280.325 150.014,281.103 150.914,281.103 151.814,281.103 150.014,282.003 150.914,282.003 151.814,282.003 150.014,282.904 150.914,282.904 151.814,282.904 107.039,327.546 108.039,327.546 107.039,328.546 108.039,328.546 112.67,331.021 113.67,331.021 112.67,332.021 113.67,332.021 149.744,348.735 150.744,348.735 149.744,349.735 150.744,349.735
  other v9: 194.597,328.06 201.257,328.06 194.597,328.86 200.457,329.66 201.257,330.46 172.476,331.26 182.336,331.26 201.257,331.26 172.476,332.06 195.397,332.06 178.336,332.86 201.257,332.86 172.476,333.66 195.392,333.667 166.076,335.26 177.536,335.26 195.392,335.267 200.457,335.26 177.536,336.86 200.457,336.86 195.392,340.067
  other v11: 52.801,349.155 53.821,349.155 54.841,349.155 55.861,349.155 52.801,350.175 53.821,350.175 54.841,350.175 55.861,350.175 52.801,351.195 53.821,351.195 54.841,351.195 55.861,351.195 52.801,352.215 53.821,352.215 54.841,352.215 55.861,352.215
  other v13: 75.769,285.72 74.924,286.567 75.769,286.567 76.594,286.567 75.769,287.417 518.223,289.525 517.379,290.373 518.223,290.373 519.048,290.373 518.223,291.223 102.07,385.766 101.225,386.613 102.07,386.613 102.895,386.613 102.07,387.463
  other v14: 66.65,205.714 66.599,207.218
eMMC_PG1: R340.1 U40.5
eMMC_PG2: R343.1 R345.2 U42.5
eMMC_rst: R99.1 R797.1 U41.K5 | length 10.4
  L1 w0.254: U41.K5@122.938,319.091 v16(122.949,319.091)
  L3 (Sign) w0.098: v16(122.949,319.091) 123.199,319.341 124.94,319.341 130.638,313.643 130.831,313.643
eMMC_Vcc: C517.2 C518.2 C523.2 C586.2 FB25.1 R339.2 R340.2 U40.8 U41.E6 U41.F5 U41.J10 U41.K9
eMMC_VccQ: C519.2 C520.2 C524.2 C587.2 FB25.2 R342.2 R343.2 U41.C6 U41.M4 U41.N4 U41.P3 U41.P5 U42.8
eMMC_Vddim: C521.2 C522.2 U41.C2
EN1: U35_I2C_Expander2.23 U61.20
EN1_TPS: R277.2 R278.2 U34.14 U34.27 U70.20 | length 21.1
  L1 w0.254: R278.2@64.339,240.856 64.783,240.856 65.822,239.817 U34.27@65.822,237.639 ; v6(65.39,229.317) 65.295,229.412 65.295,231.213 65.815,231.733 65.815,232.984 65.82,232.989 65.82,233.137 U34.14@65.822,233.139
  L3 (Sign) w0.254: v6(65.39,229.317) 65.1,229.607 65.1,237.122 65.822,237.843 65.822,240.309 65.39,240.741 65.39,241.677
EN2: U35_I2C_Expander2.24 U61.6
EN2_TPS: R745.1 U70.6 U70.17
EN_0.85V_REG1: S5.8 U34.1 U34.8
En_0V85@2A: R296.2 R435.2 U37.14 | length 1.9
  L1 w0.254: U37.14@66.175,177.317 66.177,177.315 66.177,176.889 66.836,176.23 66.841,176.23 67.204,175.867 R296.2@67.204,175.817
EN_1V0@1.5A: R634.1 U51.3 U68.4
EN_1V8@1.5A: R633.1 U50.3 U68.5
EN_2V5@1.5A: R632.1 U49.3 U68.6
EN_3V3V_REG0: S5.6 U37.1
EN_5V_REG0: S5.7 U38.8
EN_12@8A: S5.5 U38.1
EN_Detect_KEY: R655.2
En_PCIE_I2C: 
En_PCIE_SPI: 
EN_PS_LTC6952_1: U35_I2C_Expander2.20 U59_U_5V_to_3V33.3
EN_PS_LTC6952_2: U35_I2C_Expander2.22 U59_U_5V_to_3V32.3
EN_PS_LTC6952_3: U35_I2C_Expander2.17 U59_U_5V_to_3V31.3
En_PWRSwitch_PCIE0: U17.A2
En_PWRSwitch_PCIE1: U20.A2
En_PWRSwitch_PCIE2: U21.A2
En_PWRSwitch_PCIE3: U22.A2
En_PWRSwitch_PCIE4: U23.A2
EN_SEQ_LT3504: R646.2 U67.3 U69.5
EN_SPI_A_Q0: R232_SPI_bridge3.1
EN_SPI_A_Q1: R234_SPI_bridge3.1
EN_SPI_A_Q2: R235_SPI_bridge3.2
EN_SPI_A_Q3: R237_SPI_bridge3.2
EN_SPI_A_Q4: R239_SPI_bridge3.1
EN_SPI_B_Q0: R232_SPI_bridge1.1
EN_SPI_B_Q1: R234_SPI_bridge1.1
EN_SPI_B_Q2: R235_SPI_bridge1.2
EN_SPI_B_Q3: R237_SPI_bridge1.2
EN_SPI_B_Q4: R239_SPI_bridge1.1
EN_SPI_C_Q0: R232_SPI_bridge2.1
EN_SPI_C_Q1: R234_SPI_bridge2.1
EN_SPI_C_Q2: R235_SPI_bridge2.2
EN_SPI_C_Q3: R237_SPI_bridge2.2
EN_SPI_C_Q4: R239_SPI_bridge2.1
EN_VSUP_1V2: C626.2 R309.1 U19.12
EN_VSUP_1V8: C625.2 R308.1 U19.15
EN_VSUP_3V3: C624.2 R305.1 U19.14
Enable_CLK: U12.40 U13.40 U14.40
EXPANDER_RESET: J21.2 P13.2 R811.1
Ext_EZS_N: R82.1 U1.AK6 U12.48
Ext_EZS_P: R82.2 U1.AK7 U12.47
FB1/FB2: R271.1 R273.2 U34.10 U34.31 | length 12.3
  L1 w0.254: R271.1@61.041,239.87 61.041,239.82 v24(61.441,239.42) ; v17(62.82,232.364) 63.543,232.364 63.82,232.64 63.82,233.137 U34.10@63.822,233.139 ; R273.2@62.939,239.52 62.822,239.403 v17(62.822,238.22) 62.831,238.229 63.571,238.229 63.82,237.981 63.82,237.641 U34.31@63.822,237.639
  L16 w0.254: v24(61.441,239.42) 62.674,239.42 62.774,239.52 v24(62.814,239.52) ; v17(62.82,232.364) 62.821,232.365 v17(62.822,238.22) v17(62.822,238.22)
FB1_1: R287.1 R290.2 U37.31
FB1_2: R626.1 R627.2 U38.31 | length 3.3
  L1 w0.254: R626.1@59.997,209.711 60.008,209.722 60.932,209.722 R627.2@60.944,209.733 61.102,209.575 62.252,209.575 62.453,209.374 U38.31@62.453,208.714
FB2_1: R297.1 R300.2 U37.10 | length 4.1
  L1 w0.254: R300.2@61.068,175.851 R297.1@62.14,175.851 62.14,176.257 62.455,176.572 63.749,176.572 64.175,176.997 U37.10@64.175,177.317
FB2_2: R315.1 R318.2 U38.10 | length 3.5
  L1 w0.254: R318.2@60.114,202.723 R315.1@61.041,202.723 61.041,203.148 61.384,203.491 62.28,203.491 62.453,203.664 U38.10@62.453,204.214
Flag_PWRSwitch_PCIE0: R602.2 U17.A3
Flag_PWRSwitch_PCIE1: R603.2 U20.A3
Flag_PWRSwitch_PCIE2: R604.2 U21.A3
Flag_PWRSwitch_PCIE3: R605.2 U22.A3
Flag_PWRSwitch_PCIE4: R606.2 U23.A3
FPGA_Vcc_HD: C605.2 C606.2 C607.2 C610.2 C611.2 C756.2 C759.2 L16.2 R212.2 R365.1 R395.2 R398.2 R618.2 R659.2 R660.2 R661.2 R662.2 R663.2 R664.2 R688.2 R744.2 R817.2 R818.2 R819.2 R820.2 R821.2 R822.2 R823.2 R824.2 U1.AA4 U1.AC15 U1.AD3 U1.AD8 U1.AE11 U1.AF14 U1.AG7 U1.AG17 U1.AH10 U1.D13 U1.E10 U1.E16 U1.G10 U1.G12 U1.H15 U1.H25 U1.K25 U1.L27 U15.1 U15.7 U15.8 U15.16 U36_U_Translator_I2C1.2 U36_U_Translator_I2C4.2 U79.15
  other v2: 185.397,290.539 182.397,291.539 188.397,294.539 185.397,295.539 166.397,297.539 168.397,297.539 189.397,297.539 186.397,298.539 168.397,299.539 165.397,300.539 187.397,301.539 169.397,302.539 184.397,302.539 166.397,303.539 188.397,304.539 169.397,312.539 171.397,312.539 172.397,314.539
FPGA_Vcc_HP: R363.1 R364.1 R506.1 R507.1 R514.1 R515.1 R522.1 R523.1 R530.1 R531.1 R546.1 R547.1 R548.1 R549.1 R550.1 R551.1 R552.1 R553.1 R554.1 R555.1 R556.1 R557.1 R735.1
FTD_DS_Dir1: R411.2 R412.2 U56.1
FTD_DS_Dir2: R413.2 R414.2 U56.2
FTD_DS_Dir3: R415.2 R416.2 U56.7
FTD_DS_Dir4: R418.2 R421.2 U56.8
FTD_JTAG_Dir1: R402.2 R403.2 U53.1
FTD_JTAG_Dir2: R404.2 R405.2 U53.2
FTD_JTAG_Dir3: R406.2 R407.2 U53.7
FTD_JTAG_Dir4: R408.2 R409.2 U53.8
FTD_U1_DIR1: R722.2 R723.2 U79.1
FTD_U1_DIR2: R724.2 R725.2 U79.2
FTD_U1_DIR3: R726.2 R727.2 U79.7
FTD_U1_DIR4: R728.2 R729.2 U79.8
FTD_U_DIR1: R636.2 R637.2 U57.1
FTD_U_DIR2: R638.2 R639.2 U57.2
FTD_U_DIR3: R640.2 R641.2 U57.7
FTD_U_DIR4: R642.2 R643.2 U57.8
FTDI_5V: C559.2 C560.2 C563_5V_to_3V3_for_FTDI.2 C564_5V_to_3V3_for_FTDI.2 FB31.1 U59_5V_to_3V3_for_FTDI.1 U59_5V_to_3V3_for_FTDI.2 U59_5V_to_3V3_for_FTDI.3
FTDI_DM: C558.2 D15.2 U55.7
FTDI_DP: C558.3 D15.1 U55.8
FTDI_EECLK: R417.2 U54.4 U55.62
FTDI_EECS: R420.2 U54.5 U55.63
FTDI_EED: R419.1 U54.3 U55.61
FTDI_GND: C559.1 C560.1 C563_5V_to_3V3_for_FTDI.1 C564_5V_to_3V3_for_FTDI.1 C565_5V_to_3V3_for_FTDI.1 C566_5V_to_3V3_for_FTDI.1 C567_5V_to_3V3_for_FTDI.1 C658.1 C659.1 C660.1 C661.1 C662.1 C663.1 C664.1 C665.1 C666.1 C667.1 C668.1 C669.1 C670.1 C671.1 C673.1 C791.1 FB32.1 R403.1 R405.1 R407.1 R409.1 R412.1 R414.1 R416.1 R421.1 R423.1 R432_5V_to_3V3_for_FTDI.1 R637.1 R639.1 R641.1 R643.1 R723.1 R725.1 R727.1 R729.1 U53.10 U54.2 U55.1 U55.5 U55.10 U55.11 U55.13 U55.15 U55.25 U55.35 U55.47 U55.51 U56.10 U57.10 U59_5V_to_3V3_for_FTDI.4 U59_5V_to_3V3_for_FTDI.9 U77.2 U79.10 X8.2 X8.4
  other v3: 293.848,120.188 294.848,120.188 293.848,121.188 294.848,121.188
FTDI_JTAG_ON: U55.21
FTDI_JTAG_ON_1: R401.1 U53.9
FTDI_JTAG_ON_2: R410.1 U56.9
FTDI_JTAG_ON_3: R635.1 U57.9
FTDI_JTAG_ON_4: R721.1 U79.9
FTDI_LS_UART0_RXD: U55.27 U79.4
FTDI_LS_UART0_TXD: U55.26 U79.3
FTDI_LS_UART2_CTS_B: U55.41
FTDI_LS_UART2_RTS_B: U55.40
FTDI_LS_UART2_RXD: U55.39 U57.6
FTDI_LS_UART2_TXD: U55.38 U57.5
FTDI_LS_UART_RXD: U55.52 U57.4
FTDI_LS_UART_TXD: U55.48 U57.3
FTDI_PS_POR: U55.23 U77.1
FTDI_PS_SRST+B: U55.24 U77.3
FTDI_Sock_GND: C558.5 FB32.2
FTDI_TCK: P12.5 R732.1 U53.5 U55.16 U56.5
FTDI_TDI: P12.9 R734.1 U53.3 U55.17 U56.3
FTDI_TDO: P12.7 R733.1 U53.6 U55.18 U56.6
FTDI_TMS: P12.3 R731.1 U53.4 U55.19 U56.4
FTDI_VBUS: C558.1 FB31.2
FTDI_VCC1P8: C665.2 C666.2 C667.2 C673.2 U55.12 U55.37 U55.49 U55.64
FTDI_VccIO: C565_5V_to_3V3_for_FTDI.2 C566_5V_to_3V3_for_FTDI.2 C567_5V_to_3V3_for_FTDI.2 C658.2 C668.2 C669.2 C670.2 C671.2 C791.2 FB43.1 FB44.1 R401.2 R402.1 R404.1 R406.1 R408.1 R410.2 R411.1 R413.1 R415.1 R417.1 R418.1 R420.1 R422.2 R424.1 R430_5V_to_3V3_for_FTDI.2 R431_5V_to_3V3_for_FTDI.2 R635.2 R636.1 R638.1 R640.1 R642.1 R721.2 R722.1 R724.1 R726.1 R728.1 U53.16 U54.6 U55.20 U55.31 U55.42 U55.50 U55.56 U56.16 U57.16 U59_5V_to_3V3_for_FTDI.8 U77.5 U79.16
FTDI_X_IN: C663.2 U55.2 X8.1
FTDI_X_OUT: C664.2 U55.3 X8.3
GEM3_MDC: R815.1
GEM3_MDIO: R816.1
GND_PCIe_PCIE0: C1_PCIE0.1 C2_PCIE0.1 C3_PCIE0.1 J1_PCIE0.1 J1_PCIE0.3 J1_PCIE0.9 J1_PCIE0.15 J1_PCIE0.21 J1_PCIE0.24 J1_PCIE0.27 J1_PCIE0.30 J1_PCIE0.33 J1_PCIE0.34 J1_PCIE0.38 J1_PCIE0.39 J1_PCIE0.42 J1_PCIE0.45 J1_PCIE0.48 J1_PCIE0.51 J1_PCIE0.54 J1_PCIE0.57 J1_PCIE0.59 J1_PCIE0.61 J1_PCIE0.63 J1_PCIE0.65 J1_PCIE0.67
GND_PCIe_PCIE1: C1_PCIE1.1 C2_PCIE1.1 C3_PCIE1.1 J1_PCIE1.1 J1_PCIE1.3 J1_PCIE1.9 J1_PCIE1.15 J1_PCIE1.21 J1_PCIE1.24 J1_PCIE1.27 J1_PCIE1.30 J1_PCIE1.33 J1_PCIE1.34 J1_PCIE1.38 J1_PCIE1.39 J1_PCIE1.42 J1_PCIE1.45 J1_PCIE1.48 J1_PCIE1.51 J1_PCIE1.54 J1_PCIE1.57 J1_PCIE1.59 J1_PCIE1.61 J1_PCIE1.63 J1_PCIE1.65 J1_PCIE1.67
GND_PCIe_PCIE2: C1_PCIE2.1 C2_PCIE2.1 C3_PCIE2.1 J1_PCIE2.1 J1_PCIE2.3 J1_PCIE2.9 J1_PCIE2.15 J1_PCIE2.21 J1_PCIE2.24 J1_PCIE2.27 J1_PCIE2.30 J1_PCIE2.33 J1_PCIE2.34 J1_PCIE2.38 J1_PCIE2.39 J1_PCIE2.42 J1_PCIE2.45 J1_PCIE2.48 J1_PCIE2.51 J1_PCIE2.54 J1_PCIE2.57 J1_PCIE2.59 J1_PCIE2.61 J1_PCIE2.63 J1_PCIE2.65 J1_PCIE2.67
GND_PCIe_PCIE3: C1_PCIE3.1 C2_PCIE3.1 C3_PCIE3.1 J1_PCIE3.1 J1_PCIE3.3 J1_PCIE3.9 J1_PCIE3.15 J1_PCIE3.21 J1_PCIE3.24 J1_PCIE3.27 J1_PCIE3.30 J1_PCIE3.33 J1_PCIE3.34 J1_PCIE3.38 J1_PCIE3.39 J1_PCIE3.42 J1_PCIE3.45 J1_PCIE3.48 J1_PCIE3.51 J1_PCIE3.54 J1_PCIE3.57 J1_PCIE3.59 J1_PCIE3.61 J1_PCIE3.63 J1_PCIE3.65 J1_PCIE3.67
GND_PCIe_PCIE4: C1_PCIE4.1 C2_PCIE4.1 C3_PCIE4.1 J1_PCIE4.1 J1_PCIE4.3 J1_PCIE4.9 J1_PCIE4.15 J1_PCIE4.21 J1_PCIE4.24 J1_PCIE4.27 J1_PCIE4.30 J1_PCIE4.33 J1_PCIE4.34 J1_PCIE4.38 J1_PCIE4.39 J1_PCIE4.42 J1_PCIE4.45 J1_PCIE4.48 J1_PCIE4.51 J1_PCIE4.54 J1_PCIE4.57 J1_PCIE4.59 J1_PCIE4.61 J1_PCIE4.63 J1_PCIE4.65 J1_PCIE4.67
GPIO_ETH_EXPANDER: R715.1 U76.2
GPIO_Exp0_Adress0: R492.1 R493.1
GPIO_Exp0_Adress1: R494.1 R495.1
GPIO_Exp0_Adress2: R496.1 R497.1
GPIO_Exp0_Int0: R661.1 U1.AA6
  other v2: 182.397,293.539
GPIO_Exp0_Int1: R662.1 U1.AA5
  other v2: 182.397,292.539
GPIO_Exp1_Adress0: R500.1 R501.1
GPIO_Exp1_Adress1: R502.1 R503.1
GPIO_Exp1_Adress2: R504.1 R505.1
GPIO_Exp1_Int0: R663.1 U1.AD2
  other v2: 185.397,289.539
GPIO_Exp1_Int1: R664.1 U1.AE2
  other v2: 186.397,289.539
GPIO_Exp2_Adress0: R508.1 R509.1
GPIO_Exp2_Adress1: R510.1 R511.1
GPIO_Exp2_Adress2: R512.1 R513.1
GPIO_Exp2_Int0: R688.1 U1.AD1
  other v2: 185.397,288.539
GPIO_Exp2_Int1: R744.1 U1.AE1
  other v2: 186.397,288.539
GPIO_Exp3_Adress0: R516.1 R517.1
GPIO_Exp3_Adress1: R518.1 R519.1
GPIO_Exp3_Adress2: R520.1 R521.1
GPIO_Exp3_Int0: R817.1 U1.AC3
  other v2: 184.397,290.539
GPIO_Exp3_Int1: R818.1 U1.AC2
  other v2: 184.397,289.539
GPIO_Exp4_Adress0: R524.1 R525.1
GPIO_Exp4_Adress1: R526.1 R527.1
GPIO_Exp4_Adress2: R528.1 R529.1
GPIO_Exp4_Int0: R819.1 U1.AA3
  other v2: 182.397,290.539
GPIO_Exp4_Int1: R820.1 U1.AB3
  other v2: 183.397,290.539
GPIO_Exp5_Adress0: R697.1 R698.1
GPIO_Exp5_Adress1: R699.1 R700.1
GPIO_Exp5_Adress2: R701.1 R702.1
GPIO_Exp5_Int0: R821.1 U1.AB1
  other v2: 183.397,288.539
GPIO_Exp5_Int1: R822.1 U1.AC1
  other v2: 184.397,288.539
GPIO_Exp6_Adress0: R703.1 R704.1 U35_I2C_Expander_16.13
GPIO_Exp6_Adress1: R705.1 R706.1 U35_I2C_Expander_16.12
GPIO_Exp6_Adress2: R707.1 R708.1 U35_I2C_Expander_16.11
GPIO_Exp6_Int0: R823.1 U1.AA2 U35_I2C_Expander_16.16
  other v2: 182.397,289.539
GPIO_Exp6_Int1: R824.1 U1.AA1 U35_I2C_Expander_16.15
  other v2: 182.397,288.539
GPIO_Exp_Reset0: R746.1
GPIO_Exp_Reset1: R747.1
GPIO_Exp_Reset1.SCL: R559_I2C_Bridge_2.1 U3_I2C_Bridge_2.2
GPIO_Exp_Reset1.SDA: R560_I2C_Bridge_2.1 U3_I2C_Bridge_2.1
GPIO_Exp_Reset2: R748.1
GPIO_Exp_Reset3: R749.1
GPIO_Exp_Reset4: R750.1
GPIO_Exp_Reset5: R751.1
GPIO_Exp_Reset6: R752.1 U35_I2C_Expander_16.14
Ground: C63.2 C64.2 C67.2 C70.2 C75.2 C76.2 C77.2 C78.1 C79.1 C80.1 C81.2 C82.2 C83.2 C88.2 C89.2 C90.2 C91.2 C92.2 C93.2 C96.2 C99.1 C100.1 C101.1 C102.1 C103.1 C104.1 C105.1 C106.1 C107.1 C108.1 C109.1 C110.1 C124.1 C125.1 C126.1 C127.1 C141.1 C142.1 C143.1 C144.1 C145.1 C146.1 C147.1 C148.1 C162.1 C163.1 C164.1 C165.1 C179.1 C180.1 C572.1 C574.1 C575.1 C576.1 C578.1 C579.1 C590.1 C591.1 C592.1 FB36.2 R437.1 R439.1 R545.1 U16.44 U16.65 U61.3 U61.8 U61.13 U61.18 U61.21 X9.2
  other v3: 207.596,407.546 208.496,407.546 209.396,407.546 207.596,408.446 208.496,408.446 209.396,408.446 207.596,409.346 208.496,409.346 209.396,409.346 189.86,418.916 191.05,418.916 192.24,418.916 193.43,418.916 194.62,418.916 188.64,420.136 189.86,420.136 191.05,420.136 192.24,420.136 193.43,420.136 194.62,420.136 195.84,420.136 188.64,421.326 189.86,421.326 191.05,421.326 192.24,421.326 193.43,421.326 194.62,421.326 195.84,421.326 188.64,422.516 189.86,422.516 191.05,422.516 192.24,422.516 193.43,422.516 194.62,422.516 195.84,422.516 188.64,423.706 189.86,423.706 191.05,423.706 192.24,423.706 193.43,423.706 194.62,423.706 195.84,423.706 188.64,424.896 189.86,424.896 191.05,424.896 192.24,424.896 193.43,424.896 194.62,424.896 195.84,424.896 189.86,426.116 191.05,426.116 192.24,426.116 193.43,426.116 194.62,426.116
Ground_PWR_PoE: C702.1 C703.1 C704.1 D27.2 R159.1 R160.1 R667.1 R670.2 U65.3 U65.8 U65.21 | length 4.9
  L1 w0.254: v1(37.668,199.124) R670.2@37.668,199.938 ; v1(38.76,201.663) U65.3@38.76,202.478 ; v1(40.17,199.307) C702.1@40.17,200.121 ; U65.8@40.6,204.318 v1(41.478,204.318) ; v1(42.978,201.451) R667.1@42.978,202.265 ; R160.1@42.978,203.203 v1(43.793,203.203)
  other v3: 38.21,203.768 39.31,203.768 38.21,204.868 39.31,204.868
HI_Speed_En_PCIE0: 
HI_Speed_En_PCIE1: 
HI_Speed_En_PCIE2: 
HI_Speed_En_PCIE3: 
HI_Speed_En_PCIE4: 
HI_Speed_PWR_En: 
HI_Speed_PWR_En_I2C: 
HI_Speed_PWR_En_SPI: 
HI_Speed_PWR_nRST: 
HW_Conf_05028: R128.1 R129.1 U16.64
I2C0_En: 
I2C0_Reset: 
I2C0Master_SCL: J12.1 R85.1 R774.1 U36_U_Translator_I2C3.3
I2C0Master_SDA: J12.2 R86.1 R775.1 U36_U_Translator_I2C3.4
I2C1_En: U35_I2C_Expander1.19
I2C1_Reset: U35_I2C_Expander1.17
I2C1Master_SCL: J13.1 R83.1 R772.1 U36_U_Translator_I2C2.3
I2C1Master_SDA: J13.2 R84.1 R773.1 U36_U_Translator_I2C2.4
I2C_05028_SCL: R130.2 R132.1 U16.36
I2C_05028_SDA: R131.2 R134.1 U16.35
I2C_SCL_SFP0: R559_I2C_Bridge_3.1 U3_I2C_Bridge_3.2
I2C_SCL_SFP1: R227_I2C_Bridge_3.1 U3_I2C_Bridge_3.4
I2C_SCL_SFP2: R225_I2C_Bridge_3.1 U3_I2C_Bridge_3.6
I2C_SCL_SFP3: R223_I2C_Bridge_3.1 U3_I2C_Bridge_3.8
I2C_SDA_SFP0: R560_I2C_Bridge_3.1 U3_I2C_Bridge_3.1
I2C_SDA_SFP1: R558_I2C_Bridge_3.1 U3_I2C_Bridge_3.3
I2C_SDA_SFP2: R226_I2C_Bridge_3.1 U3_I2C_Bridge_3.5
I2C_SDA_SFP3: R224_I2C_Bridge_3.1 U3_I2C_Bridge_3.7
I2CFPGA_Master_SCL: R363.2 U1.AG1 U36_U_Translator_I2C1.3 U36_U_Translator_I2C4.3
  other v2: 188.397,288.539
I2CFPGA_Master_SDA: R364.2 U1.AF3 U36_U_Translator_I2C1.4 U36_U_Translator_I2C4.4
  other v2: 187.397,290.539
ILIM1: C345.2 R610.1 U34.26 | length 3.2
  L1 w0.254: U34.26@66.321,237.64 C345.2@66.32,239.69 66.38,239.63 67.318,239.63 R610.1@67.378,239.57
ILIM1_1: C389.2 R619.1 U37.26 | length 2.5
  L1 w0.254: U37.26@66.675,181.817 66.675,182.331 67.04,182.696 67.474,182.696 C389.2@68.211,183.433
ILIM1_2: C430.2 R625.2 U38.26 | length 3
  L1 w0.254: U38.26@64.953,208.714 64.953,209.219 65.973,210.239 66.991,210.239 R625.2@67.001,210.229
ILIM2: C349.2 R611.1 U34.15 | length 3.5
  L1 w0.254: C349.2@66.055,231.087 66.075,231.067 R611.1@67.093,231.067 ; U34.15@66.322,233.139 66.322,232.29 66.315,232.283 66.94,231.658 66.94,231.22 R611.1@67.093,231.067 ; R611.1@67.113,231.047 R611.1@67.093,231.067
ILIM2_1: C393.2 R620.1 U37.15 | length 2.6
  L1 w0.254: U37.15@66.675,177.317 66.675,176.892 66.983,176.584 67.861,176.584 68.185,176.26 C393.2@68.185,175.817
ILIM2_2: C434.2 R302.2 U38.15 | length 2.6
  L1 w0.254: U38.15@64.953,204.214 64.955,204.212 64.955,203.839 65.578,203.216 C434.2@65.578,202.764 66.405,202.764 66.453,202.812 R302.2@66.453,202.813
IMU_INT1: R426.1 R530.2 U1.AD11 U58.4
  other v2: 185.397,298.539
IMU_INT2: R425.1 R531.2 U1.AD10 U58.9
  other v2: 185.397,297.539
InSel_05028_00: U16.20
InSel_05028_01: U16.17
InSel_05028_10: U16.28
InSel_05028_11: U16.29
INTA_EXP_MAIN: U1.AE3
  other v2: 186.397,290.539
INTB_EXP_MAIN: U1.Y1
  other v2: 181.397,288.539
Interrupt0: R506.2 U1.AC12 U64_U_Pomiar_pradu_napiecia_3.3
  other v2: 184.397,299.539
Interrupt1: R507.2 U1.AD12 U64_U_Pomiar_pradu_napiecia_4.3
  other v2: 185.397,299.539
Interrupt2: R514.2 U1.AA12 U64_U_Pomiar_pradu_napiecia_5.3
  other v2: 182.397,299.539
Interrupt3: R515.2 U1.AA11 U64_U_Pomiar_pradu_napiecia_6.3
  other v2: 182.397,298.539
Interrupt4: R522.2 U1.AB11 U35_I2C_Expander1.16
  other v2: 183.397,298.539
Interrupt5: R523.2 U1.AC11 U72.3
  other v2: 184.397,298.539
Interrupt8: R546.2 U1.AB10 U35_I2C_Expander3.16
  other v2: 183.397,297.539
Interrupt9: R547.2 U1.AB9 U35_I2C_Expander3.15
  other v2: 183.397,296.539
Interrupt10: R548.2 U1.Y10
  other v2: 181.397,297.539
Interrupt11: R549.2 U1.AA10 U35_I2C_Expander1.23 U64_U_Pomiar_pradu_napiecia_1.3
  other v2: 182.397,297.539
Interrupt12: R550.2 U1.AC9 U35_I2C_Expander1.24 U64_U_Pomiar_pradu_napiecia_2.3
  other v2: 184.397,296.539
Interrupt13: R551.2 U1.AD9 U35_I2C_Expander1.15
  other v2: 185.397,296.539
Interrupt14: R552.2 U1.AC6
  other v2: 184.397,293.539
Interrupt15: R553.2 U1.AD6
  other v2: 185.397,293.539
Interrupt16: R554.2 U1.W8 U64_U_Pomiar_pradu_napiecia_7.3
  other v2: 180.397,295.539
Interrupt17: R555.2 U1.Y8 U64_U_Pomiar_pradu_napiecia_8.3
  other v2: 181.397,295.539
Interrupt18: R556.2 U1.Y7 U64_U_Pomiar_pradu_napiecia_9.3
  other v2: 181.397,294.539
Interrupt19: R557.2 U1.AA7 U64_U_Pomiar_pradu_napiecia_10.3
  other v2: 182.397,294.539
